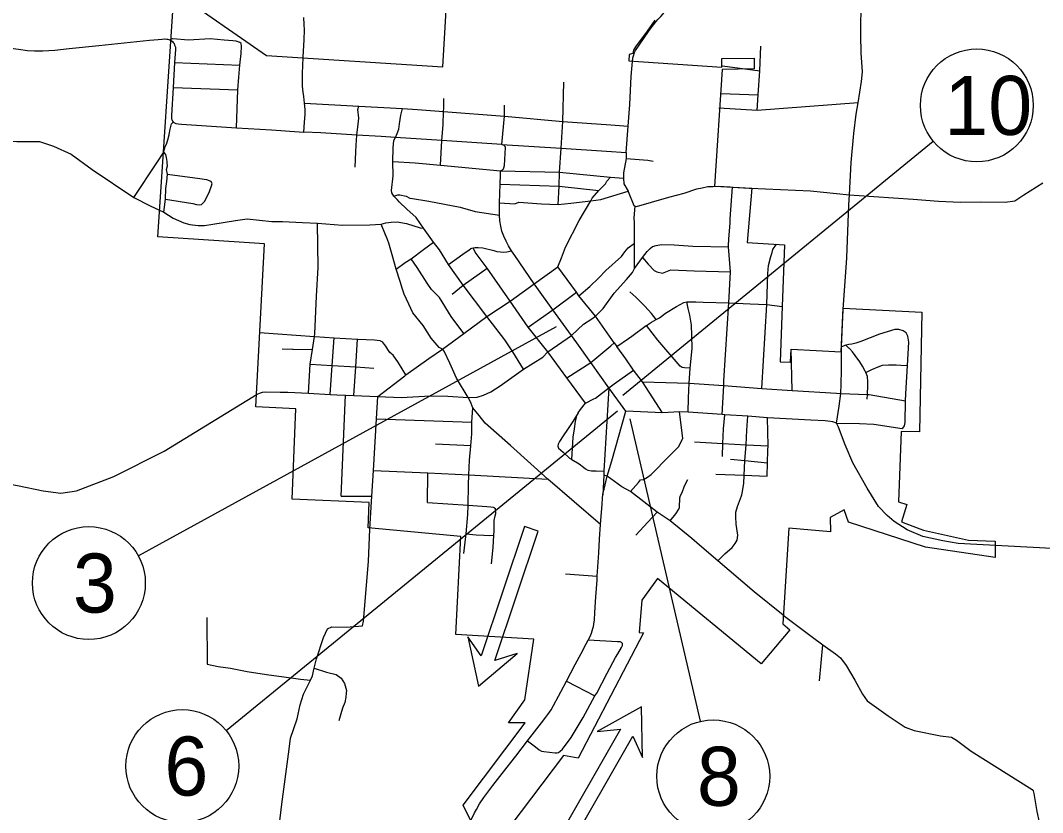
# Model space of a CAD drawing. Extents: x 2025369 to 2161369, y 549489 to 637489.
# Drawn here: x 2044367 to 2056140, y 618925 to 628050 of the extents above; entities that cross this region are included whole.
import ezdxf

# ---------------------------------------------------------------- set-up
doc = ezdxf.new("R2010")
doc.units = 0
for name, color, linetype in [('GM_X_City_Street', 7, 'Continuous'), ('GM_X_Corporation', 7, 'Continuous'), ('GM_X_County_Road', 7, 'Continuous'), ('GM_X_State_Route', 7, 'Continuous'), ('GM_X_Township_Road', 7, 'Continuous'), ('GM_X_Township_Subdivision', 7, 'Continuous'), ('SH_Text', 7, 'Continuous')]:
    doc.layers.add(name, color=color, linetype=linetype)

msp = doc.modelspace()

# ---------------------------------------------------------------- linework, layer by layer
at = {"layer": 'GM_X_City_Street'}
for points in [[(2046085, 627827), (2046123, 627843), (2046302, 627827), (2046551, 627840), (2046714, 627826), (2046814, 627819), (2046849, 627815), (2046888, 627801)], [(2046892, 627535), (2046909, 627668), (2046913, 627755), (2046908, 627784), (2046888, 627801)], [(2046143, 627567), (2046892, 627535)], [(2046854, 626814), (2046871, 627249), (2046882, 627397), (2046892, 627535)], [(2050574, 626302), (2050596, 626578), (2050614, 626887), (2050624, 627338)], [(2046126, 627276), (2046871, 627249)], [(2047640, 627095), (2048264, 627064), (2048767, 627037), (2048941, 627023), (2049241, 627000), (2049941, 626946), (2050614, 626887), (2051167, 626849), (2051368, 626832)], [(2048239, 626668), (2048243, 626730), (2048257, 626855), (2048264, 626924), (2048253, 627022), (2048264, 627064)], [(2049242, 627038), (2049245, 627151)], [(2049941, 626946), (2049941, 627072)], [(2048705, 626746), (2048727, 626797), (2048731, 626859), (2048749, 626959), (2048767, 627037)], [(2049206, 626381), (2049221, 626665), (2049235, 626847), (2049241, 627000), (2049242, 627038)], [(2049912, 626622), (2049941, 626946)], [(2048669, 626027), (2048645, 626064), (2048642, 626092), (2048659, 626258), (2048656, 626423), (2048661, 626583), (2048669, 626667), (2048686, 626700), (2048705, 626746)], [(2048222, 626359), (2048229, 626537), (2048235, 626613), (2048239, 626668)], [(2051345, 626530), (2051342, 626458), (2051312, 626293), (2051314, 626233), (2051318, 626169), (2051366, 626084), (2051367, 626081), (2051431, 625918), (2051446, 625912), (2051463, 625906)], [(2048656, 626423), (2048915, 626411), (2049206, 626381), (2049898, 626318), (2050574, 626302), (2051162, 626245), (2051314, 626233)], [(2051342, 626458), (2051595, 626440), (2051656, 626427)], [(2046059, 626279), (2046431, 626228), (2046510, 626217), (2046560, 626197)], [(2050558, 625212), (2050598, 625315), (2050646, 625438), (2050802, 625747), (2050937, 625972), (2050951, 626004), (2051029, 626089), (2051052, 626114), (2051106, 626169), (2051120, 626197), (2051162, 626245)], [(2050567, 626069), (2050571, 626139), (2050574, 626302)], [(2046454, 625930), (2046489, 625968), (2046544, 626079), (2046568, 626145), (2046574, 626170), (2046560, 626197)], [(2049892, 626164), (2050571, 626139), (2051029, 626089)], [(2051463, 625906), (2051635, 625958), (2051836, 626013), (2052010, 626062), (2052158, 626110), (2052220, 626122)], [(2052543, 625763), (2052568, 626131)], [(2046038, 625992), (2046354, 625941), (2046393, 625931), (2046428, 625926), (2046454, 625930)], [(2048669, 626027), (2048714, 626042), (2048738, 626040), (2048811, 626026), (2048850, 626003), (2048882, 625997), (2049071, 625967), (2049432, 625900), (2049606, 625850), (2049883, 625808)], [(2050163, 624034), (2050039, 624234), (2049946, 624372), (2049737, 624640), (2049468, 625002), (2049297, 625240), (2049193, 625407), (2049126, 625496), (2049008, 625658), (2048923, 625780), (2048819, 625877), (2048732, 625955), (2048704, 625988), (2048669, 626027)], [(2049883, 625948), (2050060, 625937), (2050107, 625955), (2050367, 625938), (2050560, 625930), (2050708, 625944), (2050937, 625972), (2051050, 625986), (2051366, 626084)], [(2050560, 625930), (2050567, 626069)], [(2050948, 624613), (2050990, 624642), (2051077, 624730), (2051205, 624909), (2051346, 625066), (2051415, 625147), (2051441, 625193), (2051439, 625351), (2051440, 625484), (2051440, 625558), (2051439, 625720), (2051436, 625776), (2051446, 625912)], [(2046018, 625842), (2046072, 625808), (2046127, 625772), (2046247, 625719), (2046319, 625700), (2046414, 625688), (2046487, 625687), (2046584, 625702), (2046842, 625747), (2046977, 625764), (2047263, 625735), (2047386, 625735), (2047615, 625721), (2047789, 625715), (2048077, 625692), (2048390, 625694), (2048521, 625702), (2048576, 625717), (2048636, 625725), (2048705, 625731), (2048812, 625712), (2048970, 625660), (2049008, 625658)], [(2052527, 625533), (2052540, 625715), (2052543, 625763)], [(2047683, 623755), (2047705, 624089), (2047731, 624259), (2047754, 624410), (2047758, 624438), (2047778, 624872), (2047795, 625203), (2047789, 625715)], [(2049524, 623705), (2049389, 623931), (2049314, 624101), (2049248, 624240), (2049230, 624265), (2049189, 624281), (2049099, 624390), (2049004, 624535), (2048888, 624681), (2048841, 624781), (2048787, 624898), (2048767, 624954), (2048741, 625042), (2048694, 625185), (2048647, 625349), (2048611, 625485), (2048586, 625545), (2048570, 625580), (2048521, 625702)], [(2052470, 623897), (2052527, 624795), (2052546, 625155), (2052523, 625441), (2052522, 625455), (2052527, 625533)], [(2048694, 625185), (2048799, 625261), (2048867, 625305), (2049010, 625413), (2049126, 625496)], [(2049297, 625240), (2049462, 625356), (2049536, 625409), (2049556, 625421), (2049566, 625426), (2049580, 625430)], [(2049580, 625430), (2049604, 625435), (2049621, 625436), (2049640, 625436), (2049691, 625431), (2049821, 625398), (2049853, 625390), (2049898, 625383), (2049934, 625381), (2049971, 625383), (2050023, 625395)], [(2050443, 624234), (2050214, 624518), (2050009, 624815), (2049742, 625197), (2049605, 625379), (2049580, 625430)], [(2050800, 624878), (2050924, 624984), (2051027, 625083), (2051111, 625171), (2051288, 625331), (2051328, 625383), (2051368, 625431), (2051440, 625484)], [(2051441, 625193), (2051531, 625320), (2051587, 625389), (2051622, 625423), (2051648, 625447), (2051688, 625457), (2051750, 625470), (2051895, 625465), (2052113, 625450), (2052523, 625441)], [(2053024, 625375), (2053034, 625413), (2053075, 625471)], [(2049052, 625024), (2048935, 625203), (2048867, 625305)], [(2051531, 625320), (2051596, 625241), (2051666, 625170), (2051696, 625154), (2051761, 625140), (2051858, 625178), (2052126, 625165), (2052546, 625155)], [(2052907, 623810), (2052965, 624778), (2052974, 625134), (2052985, 625228), (2053011, 625329), (2053024, 625375)], [(2048484, 623717), (2048794, 623957), (2048807, 623967), (2049072, 624156), (2049230, 624265), (2049472, 624444), (2049737, 624640), (2050009, 624815), (2050284, 625016), (2050558, 625212)], [(2049339, 624895), (2049468, 625002), (2049742, 625197)], [(2050990, 624642), (2050800, 624878), (2050771, 624919), (2050558, 625212)], [(2049472, 624444), (2049328, 624641), (2049195, 624858), (2049101, 624950), (2049052, 625024)], [(2050499, 624717), (2050771, 624919)], [(2051688, 624603), (2051636, 624674), (2051557, 624759), (2051511, 624805), (2051454, 624862), (2051385, 624924)], [(2050214, 624518), (2050499, 624717)], [(2051168, 624303), (2051206, 624335), (2051238, 624292), (2051371, 624387), (2051409, 624411), (2051573, 624534), (2051578, 624537), (2051634, 624576), (2051688, 624603), (2051728, 624623), (2051795, 624678), (2051925, 624754), (2052008, 624801), (2052042, 624808), (2052146, 624808), (2052229, 624805), (2052527, 624795)], [(2052081, 624044), (2052104, 624270), (2052101, 624420), (2052095, 624538), (2052078, 624653), (2052059, 624730), (2052042, 624808)], [(2052527, 624795), (2052771, 624784), (2052965, 624778), (2053140, 624756)], [(2050443, 624234), (2050715, 624419), (2050854, 624550), (2050948, 624613)], [(2051206, 624335), (2050990, 624642)], [(2052081, 624044), (2052015, 624048), (2051989, 624053), (2051965, 624067), (2051710, 624365), (2051578, 624537)], [(2054524, 623348), (2054532, 623352), (2054551, 623381), (2054556, 623420), (2054563, 623669), (2054565, 623747), (2054584, 624075), (2054599, 624345), (2054588, 624411), (2054568, 624451), (2054534, 624474), (2054486, 624488), (2054440, 624490), (2054350, 624463), (2054262, 624436), (2054048, 624351), (2053988, 624334), (2053944, 624322), (2053909, 624318), (2053874, 624308), (2053825, 624291)], [(2047122, 624455), (2047754, 624410), (2047759, 624409), (2047981, 624395), (2048248, 624378), (2048252, 624378), (2048443, 624370), (2048507, 624362), (2048537, 624348)], [(2047936, 623742), (2047959, 624074), (2047981, 624395)], [(2048207, 623730), (2048228, 624058), (2048248, 624378)], [(2048807, 623967), (2048723, 624104), (2048660, 624193), (2048622, 624225), (2048600, 624261), (2048575, 624297), (2048559, 624317), (2048537, 624348)], [(2047381, 624266), (2047500, 624263), (2047508, 624263)], [(2047508, 624263), (2047731, 624259)], [(2049524, 623705), (2049628, 623712), (2049702, 623732), (2049786, 623771), (2049892, 623839), (2050163, 624034), (2050384, 624172), (2050443, 624234)], [(2050874, 623641), (2050659, 623934), (2050443, 624234)], [(2050937, 624110), (2051168, 624303)], [(2051763, 623530), (2051532, 623886), (2051427, 624021), (2051339, 624152), (2051238, 624292)], [(2053254, 623787), (2053244, 624263)], [(2054121, 623686), (2054124, 623742), (2054124, 623748), (2054127, 623836), (2054129, 623886), (2054123, 623948), (2054105, 623993), (2054098, 624010), (2054064, 624066), (2054036, 624118), (2053983, 624189), (2053949, 624233), (2053918, 624272), (2053908, 624276), (2053874, 624308)], [(2050659, 623934), (2050937, 624110)], [(2047705, 624089), (2047959, 624074), (2048228, 624058), (2048439, 624046)], [(2051207, 623863), (2051427, 624021)], [(2052069, 623871), (2052081, 624044)], [(2054105, 623993), (2054172, 624030), (2054248, 624059), (2054298, 624079), (2054366, 624082), (2054452, 624084), (2054509, 624079), (2054584, 624075)], [(2051532, 623886), (2052069, 623871), (2052467, 623844), (2052907, 623810), (2053254, 623787), (2053766, 623757)], [(2052057, 623536), (2052063, 623702), (2052069, 623871)], [(2052448, 623512), (2052467, 623844), (2052470, 623897)], [(2047095, 623744), (2047132, 623759), (2047154, 623769), (2047186, 623771), (2047357, 623768), (2047359, 623768)], [(2047359, 623768), (2047447, 623767), (2047683, 623755), (2047936, 623742), (2048010, 623739), (2048110, 623734), (2048207, 623730), (2048484, 623717), (2048752, 623705), (2049091, 623725), (2049291, 623722), (2049524, 623705)], [(2050971, 623690), (2050990, 623700), (2051145, 623818), (2051207, 623863)], [(2051145, 623818), (2051087, 622859), (2051085, 622812), (2051074, 622586)], [(2053766, 623757), (2053818, 623754), (2054124, 623742), (2054141, 623741), (2054563, 623669)], [(2048061, 622571), (2048110, 623734)], [(2048390, 622189), (2048414, 622569), (2048432, 622864), (2048468, 623459), (2048484, 623717)], [(2051049, 622243), (2050440, 622765), (2050012, 623155), (2049721, 623412), (2049649, 623499), (2049577, 623587), (2049549, 623655), (2049524, 623705)], [(2050817, 623567), (2050874, 623641), (2050971, 623690)], [(2049475, 621908), (2049497, 622104), (2049499, 622136), (2049518, 622358), (2049522, 622465), (2049529, 622695), (2049533, 622817), (2049539, 622985), (2049556, 623148), (2049565, 623289), (2049565, 623422), (2049577, 623587)], [(2050789, 623529), (2050731, 623429), (2050667, 623337), (2050619, 623266), (2050576, 623200), (2050560, 623170), (2050556, 623146), (2050564, 623122), (2050617, 623078), (2050692, 623009), (2050718, 622994), (2050801, 622944), (2050851, 622905), (2050877, 622883), (2050902, 622870), (2050945, 622860), (2051000, 622861), (2051087, 622859)], [(2050718, 622994), (2050734, 623251), (2050747, 623345), (2050759, 623429), (2050771, 623478), (2050777, 623497), (2050789, 623529), (2050817, 623567)], [(2051998, 623237), (2051959, 623542)], [(2048468, 623459), (2049565, 623422)], [(2052459, 623178), (2052466, 623346), (2052480, 623507)], [(2052679, 622606), (2052698, 622715), (2052702, 622812), (2052705, 622891), (2052712, 622980), (2052726, 623163), (2052735, 623331), (2052744, 623493)], [(2052976, 623100), (2052978, 623149), (2052971, 623474)], [(2053768, 623410), (2054030, 623408), (2054197, 623398), (2054524, 623348)], [(2049556, 623148), (2049149, 623170)], [(2051485, 622729), (2051510, 622759), (2051542, 622760), (2051591, 622788), (2051630, 622820), (2051838, 623031), (2051946, 623139), (2051970, 623181), (2051998, 623237)], [(2052129, 623197), (2052459, 623178), (2052726, 623163), (2052978, 623149)], [(2052453, 623025), (2052459, 623178)], [(2052967, 622802), (2052972, 622954), (2052976, 623100)], [(2052546, 622996), (2052712, 622980), (2052972, 622954)], [(2048432, 622864), (2049060, 622837), (2049533, 622817), (2050440, 622765)], [(2049054, 622498), (2049060, 622837)], [(2052190, 622005), (2052101, 622081), (2051849, 622284), (2051699, 622384), (2051395, 622624), (2051292, 622677), (2051126, 622802), (2051085, 622812)], [(2052375, 622825), (2052702, 622812), (2052967, 622802)], [(2051395, 622624), (2051485, 622729)], [(2051849, 622284), (2051914, 622368), (2051951, 622421), (2051957, 622440), (2051961, 622549), (2051970, 622579), (2051987, 622614), (2052017, 622687), (2052055, 622760)], [(2052399, 621826), (2052482, 621905), (2052565, 621979), (2052601, 622024), (2052623, 622064), (2052630, 622122), (2052612, 622249), (2052607, 622331), (2052606, 622385), (2052626, 622449), (2052671, 622574), (2052675, 622585), (2052679, 622606)], [(2048061, 622571), (2048414, 622569)], [(2049054, 622498), (2049522, 622465), (2049739, 622449), (2049786, 622447), (2049810, 622445), (2049828, 622436), (2049838, 622428)], [(2049794, 621790), (2049811, 621980), (2049821, 622120), (2049824, 622170), (2049825, 622288), (2049836, 622344), (2049842, 622370), (2049842, 622386), (2049838, 622396), (2049840, 622410), (2049838, 622428)], [(2051595, 622271), (2051595, 622271), (2051699, 622384)], [(2051456, 622120), (2051595, 622271)], [(2049499, 622136), (2049617, 622126), (2049706, 622121), (2049766, 622115), (2049821, 622120)], [(2053154, 621200), (2052818, 621466), (2052399, 621826), (2052190, 622005)], [(2050644, 621677), (2051010, 621650)], [(2050543, 619614), (2050545, 619614), (2050564, 619619), (2050584, 619632), (2050609, 619655), (2050709, 619789), (2050850, 620021), (2050984, 620270), (2051005, 620300), (2051125, 620531), (2051219, 620710), (2051247, 620752), (2051288, 620825), (2051300, 620849), (2051300, 620861), (2051300, 620861)], [(2051300, 620861), (2051300, 620872), (2051289, 620884), (2051274, 620891), (2051245, 620891), (2050905, 620912)], [(2050656, 620440), (2050984, 620270)], [(2050208, 619750), (2050299, 619681), (2050342, 619648), (2050369, 619634), (2050395, 619630), (2050526, 619613), (2050543, 619614)]]:
    msp.add_lwpolyline(points, dxfattribs=at)
at = {"layer": 'GM_X_Corporation'}
for points in [[(2049549, 618839), (2049468, 619009), (2050179, 619957), (2049989, 619959), (2050178, 620224), (2050281, 620923), (2049382, 620976), (2049439, 622107), (2048371, 622207), (2048382, 622495), (2047495, 622537), (2047539, 623576), (2047078, 623597), (2047176, 625478), (2045949, 625559), (2046139, 628388), (2047199, 627645), (2049232, 627516), (2049320, 629021)], [(2051675, 628051), (2051584, 627925), (2051451, 627744), (2051430, 627707), (2051422, 627668), (2051377, 627659), (2051373, 627584), (2052447, 627510), (2052447, 627610), (2052817, 627617), (2052817, 627492), (2052448, 627485), (2052360, 626139), (2052793, 626119), (2052739, 625493), (2053169, 625465), (2053140, 624756), (2053116, 624119), (2053236, 624114), (2053244, 624263), (2053821, 624233), (2053844, 624736), (2054748, 624690), (2054722, 623311), (2054510, 623315), (2054481, 622503), (2054576, 622472), (2054514, 622273), (2054726, 622193), (2054769, 622178), (2055287, 622064), (2055594, 622052), (2055594, 621862), (2054793, 621982), (2053906, 622271), (2053853, 622412), (2053693, 622323), (2053696, 622158), (2053217, 622203), (2053148, 621099), (2053229, 621031), (2052897, 620640), (2051705, 621623), (2051523, 621371), (2051492, 621000), (2051544, 620996), (2050789, 619551), (2050623, 619581), (2049767, 618448)]]:
    msp.add_lwpolyline(points, dxfattribs=at)
at = {"layer": 'GM_X_County_Road'}
for points in [[(2040757, 627223), (2040829, 627219), (2041030, 627148), (2041279, 627035), (2041495, 626964), (2041736, 626871), (2041927, 626812), (2042175, 626747), (2042452, 626720), (2043556, 626706), (2044326, 626657), (2044587, 626654), (2044747, 626602), (2044950, 626509), (2045194, 626334), (2045672, 626009), (2045862, 625914), (2046018, 625842)], [(2053917, 626041), (2053934, 626414), (2053967, 626749), (2053993, 626970), (2054015, 627099), (2052852, 627012)], [(2052852, 627012), (2052411, 627039)], [(2046079, 626733), (2046079, 626734), (2046091, 626797), (2046107, 626858), (2046127, 626878)], [(2045672, 626009), (2045937, 626410), (2046018, 626534), (2046025, 626572), (2046033, 626598), (2046048, 626623), (2046065, 626675), (2046079, 626733)], [(2052220, 626122), (2052286, 626135), (2052344, 626137), (2052406, 626139), (2052540, 626133), (2052568, 626131)], [(2052568, 626131), (2052762, 626117), (2052777, 626116), (2053468, 626087), (2053917, 626041), (2053970, 626038)], [(2053970, 626038), (2054650, 625991), (2054943, 625968), (2055195, 625957), (2055425, 625960), (2055708, 625955), (2055822, 625972), (2055926, 626042), (2056143, 626179)], [(2053820, 623861), (2053825, 624021), (2053825, 624291), (2053843, 624721), (2053886, 625317), (2053910, 625927), (2053917, 626041)], [(2041117, 623775), (2041384, 623716), (2041562, 623681), (2041749, 623650), (2041957, 623616), (2042216, 623545), (2042450, 623480), (2042723, 623408), (2043061, 623246), (2043099, 623231), (2043207, 623190), (2043266, 623167), (2043474, 623062), (2043778, 622883), (2043904, 622814), (2044091, 622736), (2044333, 622691), (2044628, 622632), (2044830, 622603), (2045013, 622632), (2045443, 622795), (2046022, 623089), (2047095, 623744)], [(2053768, 623410), (2053796, 623608), (2053818, 623754), (2053820, 623861)], [(2047347, 617726), (2047297, 617946), (2047272, 618137), (2047270, 618261), (2047311, 618475), (2047379, 619021), (2047460, 619654), (2047479, 619783), (2047553, 620006), (2047587, 620166), (2047628, 620288), (2047706, 620451), (2047729, 620500), (2047750, 620589), (2047775, 620698), (2047856, 620940), (2047904, 621042), (2047952, 621066), (2048118, 621061), (2048308, 621076), (2048320, 621130), (2048377, 621817), (2048390, 622189)]]:
    msp.add_lwpolyline(points, dxfattribs=at)
at = {"layer": 'GM_X_State_Route'}
for points in [[(2051423, 627629), (2051427, 627643), (2051439, 627681), (2051451, 627705), (2051601, 627923), (2051657, 627999), (2051685, 628034), (2051713, 628066), (2051742, 628097), (2051785, 628144), (2051846, 628200), (2051907, 628256)], [(2047625, 627629), (2047634, 627826), (2047637, 627941), (2047635, 628003), (2047629, 628085)], [(2043610, 627782), (2043645, 627786), (2043710, 627789), (2043795, 627787), (2043856, 627782), (2043965, 627769), (2044142, 627745), (2044345, 627717), (2044449, 627705), (2044528, 627700), (2044625, 627699), (2044763, 627709), (2044929, 627728), (2045270, 627763), (2045706, 627807), (2045852, 627822), (2045952, 627832), (2045998, 627835), (2046031, 627836), (2046033, 627836)], [(2046033, 627836), (2046051, 627835), (2046065, 627833), (2046075, 627831), (2046085, 627827), (2046102, 627820), (2046117, 627809), (2046127, 627797), (2046136, 627783), (2046143, 627766), (2046151, 627741), (2046152, 627716), (2046143, 627567), (2046126, 627276), (2046105, 626954), (2046106, 626927), (2046107, 626916), (2046110, 626908), (2046114, 626898), (2046119, 626888), (2046127, 626878)], [(2047632, 626764), (2047639, 626877), (2047642, 626919), (2047645, 626969), (2047646, 627021), (2047643, 627064), (2047640, 627095), (2047631, 627173), (2047624, 627225), (2047620, 627257), (2047617, 627293), (2047617, 627440), (2047624, 627624), (2047625, 627629)], [(2051345, 626530), (2051368, 626832), (2051387, 627082), (2051402, 627403), (2051411, 627536), (2051415, 627576), (2051421, 627620), (2051423, 627629)], [(2046127, 626878), (2046141, 626870), (2046156, 626864), (2046182, 626858), (2046221, 626854), (2046854, 626814), (2047260, 626788), (2047632, 626764)], [(2048520, 626712), (2048243, 626730), (2047827, 626754), (2047632, 626764)], [(2049912, 626622), (2049221, 626665), (2048686, 626700), (2048520, 626712)], [(2049896, 626267), (2049898, 626318), (2049919, 626327), (2049932, 626339), (2049936, 626352), (2049942, 626378), (2049954, 626588), (2049950, 626596), (2049939, 626608), (2049912, 626622)], [(2049912, 626622), (2050596, 626578), (2051118, 626544), (2051345, 626530)], [(2049883, 625948), (2049892, 626164), (2049896, 626267)], [(2050315, 624973), (2050284, 625016), (2050060, 625341), (2050023, 625395), (2049987, 625454), (2049960, 625508), (2049934, 625566), (2049913, 625624), (2049900, 625680), (2049890, 625741), (2049883, 625808), (2049883, 625948)], [(2051339, 623550), (2051145, 623818), (2050937, 624110), (2050774, 624336), (2050715, 624419), (2050499, 624717), (2050315, 624973)], [(2051074, 622586), (2051079, 622612), (2051089, 622651), (2051126, 622802), (2051177, 622976), (2051339, 623550)], [(2053665, 623433), (2053636, 623436), (2053469, 623444), (2052971, 623474), (2052744, 623493), (2052480, 623507), (2052448, 623512), (2052057, 623536), (2051959, 623542), (2051763, 623530), (2051339, 623550)], [(2056317, 621949), (2056247, 621966), (2055166, 622026), (2054991, 622055), (2054759, 622107), (2054579, 622183), (2054430, 622277), (2054349, 622347), (2054250, 622451), (2054118, 622661), (2053956, 622954), (2053866, 623163), (2053790, 623366), (2053768, 623410), (2053723, 623428), (2053665, 623433)], [(2051053, 622292), (2051067, 622472), (2051071, 622549), (2051074, 622586)], [(2050856, 620818), (2050883, 620869), (2050905, 620912), (2050928, 620954), (2050944, 620993), (2050953, 621018), (2050961, 621047), (2050967, 621068), (2050971, 621094), (2050978, 621145), (2050983, 621230), (2050995, 621412), (2051009, 621604), (2051010, 621650), (2051028, 621918), (2051038, 622073), (2051049, 622243), (2051053, 622292)], [(2049543, 618803), (2049556, 618835), (2049566, 618857), (2049596, 618923), (2049618, 618961), (2049656, 619025), (2049705, 619098), (2049808, 619236), (2049916, 619376), (2050071, 619574), (2050208, 619750), (2050369, 619957), (2050420, 620023), (2050443, 620055), (2050479, 620110), (2050591, 620316), (2050656, 620440), (2050757, 620632), (2050847, 620801), (2050856, 620818)]]:
    msp.add_lwpolyline(points, dxfattribs=at)
at = {"layer": 'GM_X_Township_Road'}
for points in [[(2054015, 627099), (2054053, 627346), (2054067, 627456), (2054051, 627675), (2054048, 627879), (2054049, 628300), (2054059, 628653), (2054075, 629014), (2054139, 629355), (2054186, 630001), (2054188, 630084), (2054196, 630276), (2054194, 630295), (2054187, 630310), (2054167, 630338), (2054145, 630360), (2054109, 630382), (2054085, 630389), (2053947, 630418)], [(2046057, 626410), (2046057, 626424), (2046049, 626472), (2046040, 626506), (2046018, 626534)], [(2046018, 625842), (2046038, 625992), (2046041, 626112), (2046053, 626193), (2046059, 626279), (2046049, 626333), (2046059, 626376), (2046057, 626410)], [(2053154, 621200), (2053491, 620945), (2053609, 620859), (2053754, 620752), (2053812, 620708), (2053876, 620621), (2053977, 620451), (2054064, 620288), (2054119, 620212), (2054360, 620041), (2054556, 619908), (2054661, 619870), (2054965, 619810), (2055092, 619792), (2055148, 619758), (2055319, 619631), (2056020, 619191), (2056032, 619175), (2056041, 619143), (2056071, 618962), (2056075, 618938), (2056102, 618815), (2056200, 618675)], [(2053572, 620443), (2053572, 620443), (2053609, 620859)]]:
    msp.add_lwpolyline(points, dxfattribs=at)
at = {"layer": 'GM_X_Township_Subdivision'}
for points in [[(2052852, 627012), (2052865, 627193), (2052883, 627471), (2052896, 627755)], [(2052453, 627526), (2052883, 627471)], [(2052435, 627207), (2052865, 627193)], [(2046514, 621172), (2046516, 620636)], [(2046516, 620636), (2046644, 620607), (2046786, 620587), (2046978, 620551), (2047200, 620516), (2047400, 620490), (2047538, 620470), (2047592, 620461), (2047706, 620451)], [(2047750, 620589), (2047893, 620544), (2048003, 620514), (2048061, 620472), (2048100, 620411), (2048123, 620333), (2048120, 620304), (2048120, 620302)], [(2048120, 620302), (2048116, 620255), (2048103, 620194), (2048077, 620126), (2048056, 620064), (2048035, 619983)]]:
    msp.add_lwpolyline(points, dxfattribs=at)
at = {"layer": 'SH_Text'}
for p, q in [((2051304, 623734), (2054880, 626660)), ((2050538, 624522), (2045725, 621881)), ((2046735, 619872), (2051245, 623552)), ((2052200, 619977), (2051389, 623461))]:
    msp.add_line(p, q, dxfattribs=at)
for points in [[(2050331, 622167), (2050173, 622220), (2049674, 620731), (2049519, 620950), (2049644, 620380), (2050088, 620759), (2049832, 620678)], [(2050498, 618524), (2050642, 618441), (2051422, 619805), (2051532, 619560), (2051519, 620143), (2051011, 619858), (2051278, 619887)]]:
    msp.add_lwpolyline(points, close=True, dxfattribs=at)
for centre in [(2055383, 627071), (2045155, 621569), (2046231, 619461), (2052347, 619343)]:
    msp.add_circle(centre, 650, dxfattribs=at)

# ---------------------------------------------------------------- texts
for s, p in [('10', (2055009, 626731)), ('3', (2044971, 621229)), ('6', (2046025, 619121)), ('8', (2052159, 619003))]:
    msp.add_text(s, height=680, dxfattribs=at).set_placement(p)

doc.saveas('drawing.dxf')
